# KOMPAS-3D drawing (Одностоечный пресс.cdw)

Views: Вид 1, Выносной элемент А, Выносной элемент
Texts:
  ДМ 502.07.0000ТЗ
  Узел пресса
  Wik
  Егоров
  СПбГПУ
  Группа №33321/2
  ДМ 502.07.0000ТЗ-
Dimensions and other numbers on the sheet: 300; 58; 16; 63; 48; 25; 780; 22; 36x6; 60; 52; 15; 11; 40; 18; 36; 31,5; 22,5; 1:1; 1; 0; 2; 3; 4; 5; 6; 7; 8; 9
